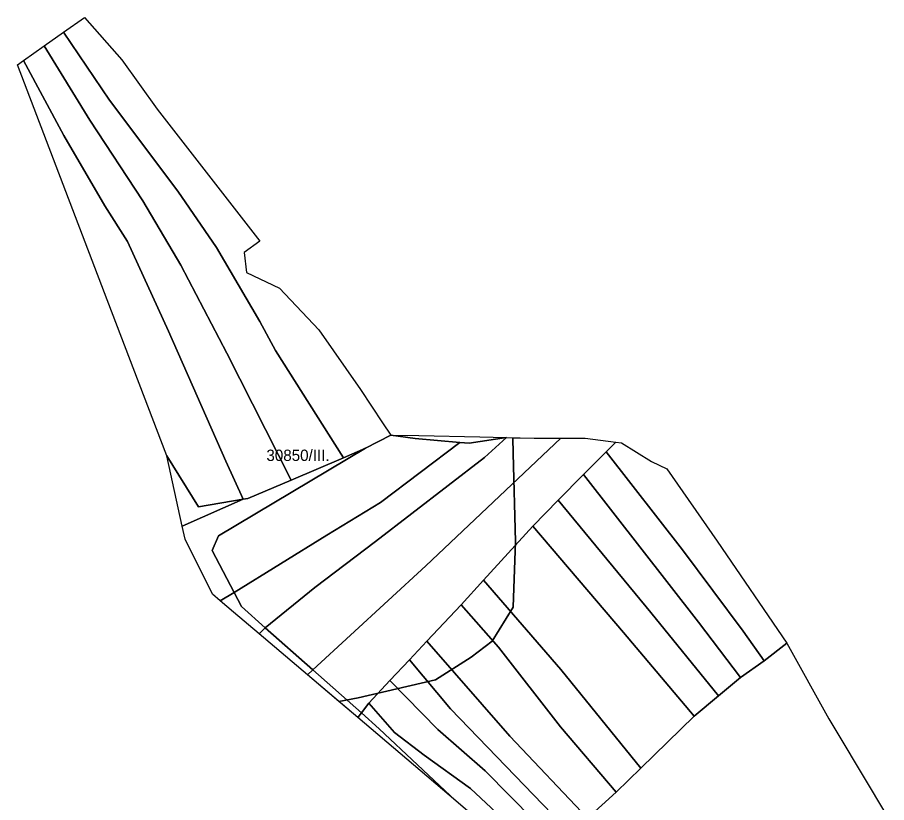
# Model space of a CAD drawing. Extents: x -537068 to -534056, y -1176840 to -1172401.
# Drawn here: x -536612.2 to -536229, y -1172747.1 to -1172401.1 of the extents above; entities that cross this region are included whole.
import ezdxf

# ---------------------------------------------------------------- set-up
doc = ezdxf.new("R2010")
doc.units = 0
for name, color, linetype in [('95560013', 7, 'Continuous'), ('95610013', 7, 'Continuous'), ('95640013', 7, 'Continuous'), ('95660013', 7, 'Continuous')]:
    doc.layers.add(name, color=color, linetype=linetype)

msp = doc.modelspace()

# ---------------------------------------------------------------- linework, layer by layer
at = {"layer": '95560013'}
for points in [[(-536609.44, -1172420.03), (-536600.44, -1172413.66), (-536580.25, -1172446.42), (-536556.93, -1172481.88), (-536540.11, -1172510.25), (-536519.86, -1172549.09), (-536491.5, -1172604.96), (-536510.55, -1172613.1), (-536512.71, -1172613.46), (-536520.3, -1172596.67), (-536545.57, -1172539.41), (-536563.62, -1172499.77), (-536573.66, -1172484.09), (-536591.74, -1172453.05)], [(-536458.7, -1172590.95), (-536447.56, -1172585.12), (-536436.85, -1172586.71), (-536417.15, -1172588.39), (-536452.09, -1172614.81), (-536475.77, -1172629.33), (-536516.66, -1172654.49), (-536526.3, -1172636), (-536523.55, -1172629.55)], [(-536481.09, -1172652.26), (-536502.91, -1172670.05), (-536513.4, -1172660.75), (-536516.66, -1172654.49), (-536475.77, -1172629.33), (-536452.09, -1172614.81), (-536417.15, -1172588.39), (-536412.99, -1172588.74), (-536396.61, -1172586.24), (-536406.21, -1172595.1), (-536454.24, -1172632.09)], [(-536502.91, -1172670.05), (-536481.09, -1172652.26), (-536454.24, -1172632.09), (-536406.21, -1172595.1), (-536396.61, -1172586.24), (-536384.28, -1172586.51), (-536372.53, -1172586.5), (-536432.05, -1172642.75), (-536481.9, -1172688.67)], [(-536431.63, -1172676.02), (-536439.38, -1172684.26), (-536447.95, -1172693.37), (-536457.25, -1172703.37), (-536460.52, -1172707.62), (-536481.9, -1172688.67), (-536432.05, -1172642.75), (-536372.53, -1172586.5), (-536361.86, -1172586.49), (-536348.38, -1172588.23), (-536352.67, -1172592.58), (-536362.54, -1172602.58), (-536373.7, -1172613.88), (-536384.91, -1172625.24), (-536406.62, -1172649.09), (-536416.56, -1172660.01)], [(-536436.85, -1172586.71), (-536447.56, -1172585.12), (-536435.22, -1172585.39), (-536408.24, -1172585.98), (-536396.61, -1172586.24), (-536412.99, -1172588.74), (-536417.15, -1172588.39)], [(-536292.16, -1172671.5), (-536318.93, -1172635.73), (-536352.67, -1172592.58), (-536348.38, -1172588.23), (-536345.78, -1172588.57), (-536332.55, -1172596.81), (-536325.88, -1172600.09), (-536303.65, -1172631.89), (-536272.95, -1172676.8), (-536282.89, -1172684.59)], [(-536318.93, -1172635.73), (-536292.16, -1172671.5), (-536282.89, -1172684.59), (-536293.45, -1172691.94), (-536311.92, -1172667.61), (-536362.54, -1172602.58), (-536352.67, -1172592.58)], [(-536362.54, -1172602.58), (-536311.92, -1172667.61), (-536293.45, -1172691.94), (-536303.04, -1172700.01), (-536332.86, -1172663.35), (-536373.7, -1172613.88)], [(-536384.91, -1172625.24), (-536373.7, -1172613.88), (-536332.86, -1172663.35), (-536303.04, -1172700.01), (-536313.77, -1172709.04), (-536344.98, -1172672.22)], [(-536313.77, -1172709.04), (-536337.37, -1172731.95), (-536372.66, -1172688.46), (-536406.62, -1172649.09), (-536384.91, -1172625.24), (-536344.98, -1172672.22)], [(-536372.66, -1172688.46), (-536337.37, -1172731.95), (-536348.25, -1172742.52), (-536372.79, -1172713.78), (-536400.1, -1172678.68), (-536416.56, -1172660.01), (-536406.62, -1172649.09)], [(-536416.56, -1172660.01), (-536400.1, -1172678.68), (-536372.79, -1172713.78), (-536348.25, -1172742.52), (-536360.89, -1172753.93), (-536395.01, -1172717.8), (-536431.63, -1172676.02)], [(-536439.38, -1172684.26), (-536431.63, -1172676.02), (-536395.01, -1172717.8), (-536360.89, -1172753.93), (-536368.3, -1172760.63), (-536421.21, -1172705.87)], [(-536373.62, -1172765.93), (-536405.96, -1172733.14), (-536426.76, -1172714.88), (-536447.95, -1172693.37), (-536439.38, -1172684.26), (-536421.21, -1172705.87), (-536368.3, -1172760.63)], [(-536426.76, -1172714.88), (-536405.96, -1172733.14), (-536373.62, -1172765.93), (-536377.53, -1172769.83), (-536382.88, -1172768.6), (-536412.39, -1172740.95), (-536432.79, -1172726.19), (-536445.97, -1172716.17), (-536457.25, -1172703.37), (-536447.95, -1172693.37)], [(-536418.9, -1172746.3), (-536452.7, -1172714.55), (-536460.52, -1172707.62), (-536457.25, -1172703.37), (-536445.97, -1172716.17), (-536432.79, -1172726.19), (-536412.39, -1172740.95), (-536382.88, -1172768.6), (-536396.7, -1172765.45)]]:
    msp.add_lwpolyline(points, close=True, dxfattribs=at)
msp.add_lwpolyline([(-536360.89, -1172753.93), (-536348.25, -1172742.52), (-536337.37, -1172731.95), (-536313.77, -1172709.04), (-536303.04, -1172700.01), (-536293.45, -1172691.94), (-536282.89, -1172684.59), (-536272.95, -1172676.8), (-536254.51, -1172710.25), (-536250, -1172717.59), (-536228.97, -1172752.63)], dxfattribs=at)
at = {"layer": '95610013'}
for points in [[(-536524.34, -1172502.44), (-536541.41, -1172477.68), (-536571.53, -1172437.51), (-536591.78, -1172407.53), (-536582.63, -1172401.06), (-536566.18, -1172419.82), (-536550.54, -1172441.5), (-536505.34, -1172499.69), (-536512.26, -1172504.73), (-536511.24, -1172513.54), (-536496.58, -1172520.33), (-536479.35, -1172538.8), (-536460.88, -1172565.06), (-536451.15, -1172579.71), (-536447.56, -1172585.12), (-536458.7, -1172590.95), (-536468.48, -1172595.13), (-536498.45, -1172547.89), (-536505.32, -1172535.03)], [(-536505.32, -1172535.03), (-536498.45, -1172547.89), (-536468.48, -1172595.13), (-536491.5, -1172604.96), (-536519.86, -1172549.09), (-536540.11, -1172510.25), (-536556.93, -1172481.88), (-536580.25, -1172446.42), (-536600.44, -1172413.66), (-536591.78, -1172407.53), (-536571.53, -1172437.51), (-536541.41, -1172477.68), (-536524.34, -1172502.44)], [(-536563.62, -1172499.77), (-536545.57, -1172539.41), (-536520.3, -1172596.67), (-536512.71, -1172613.46), (-536532.3, -1172616.75), (-536546.35, -1172594.35), (-536570.75, -1172530.47), (-536612.18, -1172421.97), (-536609.44, -1172420.03), (-536591.74, -1172453.05), (-536573.66, -1172484.09)]]:
    msp.add_lwpolyline(points, close=True, dxfattribs=at)
at = {"layer": '95640013'}
for points in [[(-536526.3, -1172636), (-536516.66, -1172654.49), (-536522.73, -1172658.22), (-536526.15, -1172655.3), (-536538.2, -1172631.05), (-536539.49, -1172625.24), (-536512.71, -1172613.46), (-536510.55, -1172613.1), (-536491.5, -1172604.96), (-536468.48, -1172595.13), (-536458.7, -1172590.95), (-536523.55, -1172629.55)], [(-536532.3, -1172616.75), (-536512.71, -1172613.46), (-536539.49, -1172625.24), (-536546.35, -1172594.35)], [(-536502.91, -1172670.05), (-536505.63, -1172672.75), (-536516.95, -1172663.15), (-536522.73, -1172658.22), (-536516.66, -1172654.49), (-536513.4, -1172660.75)], [(-536481.9, -1172688.67), (-536484.27, -1172690.86), (-536505.63, -1172672.75), (-536502.91, -1172670.05)], [(-536462.09, -1172709.68), (-536484.27, -1172690.86), (-536481.9, -1172688.67), (-536460.52, -1172707.62)], [(-536418.9, -1172746.3), (-536462.09, -1172709.68), (-536460.52, -1172707.62), (-536452.7, -1172714.55)]]:
    msp.add_lwpolyline(points, close=True, dxfattribs=at)
at = {"layer": '95660013'}
msp.add_lwpolyline([(-536396.61, -1172586.24), (-536393.81, -1172586.3), (-536393.63, -1172593.34), (-536392.62, -1172632), (-536393.62, -1172661), (-536402.87, -1172676), (-536412.19, -1172683), (-536427.81, -1172693), (-536461.87, -1172701), (-536470.46, -1172702.58), (-536484.27, -1172690.86), (-536505.63, -1172672.75), (-536516.95, -1172663.15), (-536522.73, -1172658.22), (-536526.15, -1172655.3), (-536538.2, -1172631.05), (-536539.49, -1172625.24), (-536546.35, -1172594.35), (-536570.75, -1172530.47), (-536612.18, -1172421.97), (-536609.44, -1172420.03), (-536600.44, -1172413.66), (-536591.78, -1172407.53), (-536582.63, -1172401.06), (-536566.18, -1172419.82), (-536550.54, -1172441.5), (-536505.34, -1172499.69), (-536512.26, -1172504.73), (-536511.24, -1172513.54), (-536496.58, -1172520.33), (-536479.35, -1172538.8), (-536460.88, -1172565.06), (-536451.15, -1172579.71), (-536447.56, -1172585.12), (-536435.22, -1172585.39), (-536408.24, -1172585.98)], close=True, dxfattribs=at)
msp.add_lwpolyline([(-536396.7, -1172765.45), (-536418.9, -1172746.3), (-536462.09, -1172709.68), (-536470.46, -1172702.58), (-536461.87, -1172701), (-536427.81, -1172693), (-536412.19, -1172683), (-536402.87, -1172676), (-536393.62, -1172661), (-536392.62, -1172632), (-536393.63, -1172593.34), (-536393.81, -1172586.3), (-536384.28, -1172586.51), (-536372.53, -1172586.5), (-536361.86, -1172586.49), (-536348.38, -1172588.23), (-536345.78, -1172588.57), (-536332.55, -1172596.81), (-536325.88, -1172600.09), (-536303.65, -1172631.89), (-536272.95, -1172676.8), (-536254.51, -1172710.25), (-536250, -1172717.59), (-536228.97, -1172752.63)], dxfattribs=at)

# ---------------------------------------------------------------- texts
msp.add_text('30850/III.', height=5, rotation=360, dxfattribs=at).set_placement((-536502.4, -1172596.56))

doc.saveas('drawing.dxf')
